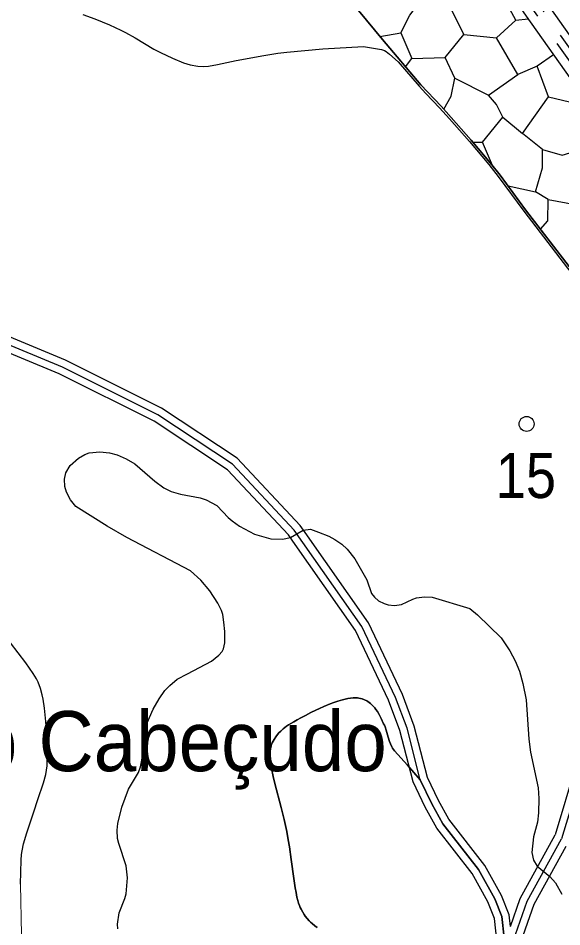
# Model space of a CAD drawing. Extents: x -64005 to -55000, y -89025 to -80000.
# Drawn here: x -58155 to -57432, y -86930 to -85720 of the extents above; entities that cross this region are included whole.
import ezdxf
from ezdxf.enums import TextEntityAlignment as Align

# ---------------------------------------------------------------- set-up
doc = ezdxf.new("R2010")
doc.units = 0
doc.header["$LTSCALE"] = 32
doc.linetypes.add('LONG_DASHED', pattern=[7.5, 6, -1.5])
for name, color, linetype, lineweight in [('1', 7, 'Continuous', 25), ('19', 7, 'Continuous', 25), ('2', 7, 'Continuous', 25), ('24', 7, 'Continuous', 25), ('39', 7, 'LONG_DASHED', 25), ('52', 7, 'Continuous', 25), ('6', 7, 'Continuous', 25), ('8', 7, 'Continuous', 25)]:
    doc.layers.add(name, color=color, linetype=linetype, lineweight=lineweight)
doc.layers.add('38', color=7, linetype='Continuous')
doc.layers.add('45', color=7, linetype='Continuous')

msp = doc.modelspace()

# ---------------------------------------------------------------- linework, layer by layer
at = {"layer": '1'}
for points in [[(-58022.62, -86932.62), (-58023.08, -86926.35), (-58020.77, -86910.96), (-58013.35, -86892.23), (-58011.68, -86885.82), (-58009.92, -86864.4), (-58011.54, -86848.71), (-58021.36, -86818.92), (-58022.93, -86812.2), (-58023.73, -86801.15), (-58022.57, -86791.95), (-58017.28, -86770.43), (-58008.67, -86746.26), (-57994.99, -86724.19), (-57992.41, -86716.67), (-57989.51, -86700.88), (-57986.13, -86668.4), (-57983.64, -86657.94), (-57975.7, -86639.8), (-57967.54, -86625.98), (-57960.05, -86615.21), (-57953.27, -86608.3), (-57943.57, -86599.99), (-57929.85, -86593.11), (-57898.08, -86576.04), (-57888.1, -86568.27), (-57884.06, -86563.32), (-57882.18, -86559.63), (-57880.41, -86551.71), (-57880.43, -86536.34), (-57881.46, -86524.08), (-57883.02, -86513.78), (-57884.68, -86508.56), (-57889.41, -86498.66), (-57900.36, -86482.24), (-57912.28, -86468.05), (-57925.94, -86455.92), (-58010.53, -86411.32), (-58037.05, -86396.29), (-58078.74, -86370), (-58085.82, -86361.23), (-58090.8, -86350.87), (-58093.06, -86343.4), (-58093.66, -86333.63), (-58091.85, -86325.19), (-58086.11, -86315.34), (-58075.12, -86305.68), (-58066.45, -86300.78), (-58060.95, -86298.85)], [(-58060.95, -86298.85), (-58046.6, -86297.24), (-58033.61, -86298.67), (-58023.54, -86301.46), (-58011.37, -86306.61), (-57999.84, -86313.53), (-57973.31, -86336.3), (-57961.31, -86345.31), (-57951.63, -86350.28), (-57939.2, -86353.8), (-57913.3, -86358.64), (-57905, -86361.23), (-57890.81, -86368.69), (-57882.9, -86377.06), (-57875.97, -86384.89), (-57870.37, -86389.28), (-57860.73, -86396.32), (-57840.89, -86406.82), (-57819.31, -86413.24), (-57803.56, -86413.83), (-57793.06, -86411.49), (-57776.14, -86401.57), (-57766.22, -86400.4), (-57755.58, -86404.08), (-57741.85, -86409.74), (-57733.88, -86413.92), (-57724.83, -86420.13), (-57717.47, -86427.07), (-57707.36, -86439.92), (-57691.53, -86467.61), (-57685.15, -86485.86), (-57681.25, -86491), (-57675.8, -86495.51), (-57668.19, -86499.43), (-57663.09, -86500.93), (-57654.49, -86501.77), (-57645.32, -86500.44), (-57630.36, -86493.36), (-57625.19, -86491.84), (-57614.74, -86490.41), (-57604.24, -86490.81), (-57554.53, -86506.04), (-57544.23, -86514.52), (-57512.82, -86545.15), (-57501.13, -86562.11), (-57494.05, -86575.42), (-57488.43, -86589.51), (-57483.64, -86605.74), (-57479.35, -86627.56), (-57475.75, -86679.87), (-57473.71, -86697.13), (-57463.41, -86744.72), (-57462.58, -86758.96), (-57462.93, -86778.13), (-57464.11, -86790.53), (-57469.48, -86809.71), (-57472, -86830.86), (-57469.57, -86840.81), (-57464.88, -86848.82), (-57448.02, -86862.68), (-57440.35, -86871.06), (-57431.91, -86886.4)]]:
    msp.add_lwpolyline(points, dxfattribs=at)
at = {"layer": '19'}
for p, q in [((-57492.92, -85722.5), (-57476.76, -85720.77)), ((-57639.92, -85784.58), (-57631.42, -85773.61)), ((-57524.16, -85916.19), (-57537.62, -85885.08))]:
    msp.add_line(p, q, dxfattribs=at)
for points in [[(-58127.34, -85120), (-57870.7, -85289.42), (-57711.55, -85422.38), (-57641.47, -85485.65), (-57474.02, -85724.68), (-57206.71, -86102.58), (-57203.97, -86106.46), (-57273.24, -86268.58)], [(-57554.12, -85671.82), (-57580.1, -85706.64), (-57562.49, -85741.88), (-57518.9, -85746.29), (-57492.92, -85722.5), (-57525.5, -85662.58)], [(-57673.9, -85744.25), (-57645.95, -85739.68), (-57634.06, -85715.88), (-57617.77, -85693.86)], [(-57273.24, -86268.58), (-57280.3, -86256.85), (-57288.99, -86240.05), (-57300.17, -86217.45), (-57306.34, -86206.47), (-57325.59, -86176.19), (-57340.53, -86153.31), (-57348.52, -86142.23), (-57380.22, -86103.46), (-57422.11, -86050.82), (-57480.14, -85974.96), (-57514.1, -85928.83), (-57526.62, -85913.1), (-57552.6, -85882.41), (-57592.51, -85837.14), (-57619.68, -85808.55), (-57670.35, -85748.55), (-57702.33, -85709.77)], [(-57645.95, -85739.68), (-57631.42, -85773.61), (-57586.95, -85772.29), (-57562.49, -85741.88)], [(-57442.91, -85768.65), (-57464.73, -85783.74), (-57490.28, -85794.76), (-57518.9, -85746.29)], [(-57589.13, -85840.98), (-57579.01, -85823.85), (-57574.18, -85800.05), (-57586.95, -85772.29)], [(-57574.18, -85800.05), (-57529.7, -85822.52), (-57490.28, -85794.76)], [(-57510.33, -85851.6), (-57484.34, -85873.63), (-57449.56, -85824.72), (-57464.73, -85783.74)], [(-57449.56, -85824.72), (-57421.82, -85831.33), (-57409.4, -85816.04)], [(-57550.23, -85885.22), (-57537.62, -85885.08), (-57510.33, -85851.6), (-57518.69, -85834.86), (-57529.7, -85822.52)], [(-57457.49, -85894.77), (-57431.52, -85902.26), (-57411.26, -85896.1), (-57401.12, -85843.22), (-57421.82, -85831.33)], [(-57503.53, -85943.19), (-57467.17, -85951.17), (-57457.49, -85919.44), (-57457.49, -85894.77), (-57484.34, -85873.63)], [(-57450.01, -85961.3), (-57414.33, -85967.91), (-57381.31, -85922.09)], [(-57460.39, -86000.77), (-57450.44, -85989.95), (-57450.01, -85961.3), (-57467.17, -85951.17)]]:
    msp.add_lwpolyline(points, dxfattribs=at)
at = {"layer": '2'}
msp.add_lwpolyline([(-58151.95, -86873.12), (-58151.22, -86840.83), (-58150.72, -86833.49), (-58150.05, -86828.65), (-58148.04, -86819.05), (-58143.86, -86804.81), (-58137.48, -86785.95), (-58134.54, -86776.51), (-58129.14, -86760.04), (-58121.63, -86738.14), (-58118.58, -86726.81), (-58116.9, -86715.22), (-58116.58, -86707.47), (-58116.77, -86691.99), (-58117.7, -86668.28), (-58118.57, -86656.43), (-58120.4, -86638.66), (-58122.1, -86626.79), (-58123.26, -86620.91), (-58125.59, -86612.25), (-58128.85, -86603.83), (-58130.91, -86599.74), (-58135.27, -86592.31), (-58144.91, -86578.33), (-58165.52, -86551.82)], dxfattribs=at)
at = {"layer": '2', "lineweight": 13}
msp.add_lwpolyline([(-58069.26, -87396.38), (-58086.31, -87327.48), (-58090.73, -87307.09), (-58093.13, -87293.38), (-58097.18, -87265.82), (-58101.96, -87228.09), (-58110.24, -87152.53), (-58110.75, -87146.28), (-58111.12, -87133.69), (-58111.5, -87116.9), (-58112.2, -87108.58), (-58113.58, -87100.37), (-58114.59, -87096.31), (-58119.23, -87080.74), (-58129.1, -87049.88), (-58145.06, -86999.71), (-58146.77, -86993.31), (-58149.06, -86980.3), (-58150.21, -86967.11), (-58150.86, -86940.59), (-58151.95, -86873.12)], dxfattribs=at)
at = {"layer": '24'}
for points in [[(-58069.4, -85715.19), (-58053.37, -85720.84), (-58033.97, -85728.97), (-58018.74, -85735.95), (-58012.25, -85739.21), (-57999.7, -85746.27), (-57974.73, -85761.11), (-57965.98, -85765.82), (-57949.94, -85773.45), (-57935.4, -85779.39), (-57926.6, -85782.08), (-57916.29, -85783.99), (-57908.9, -85784.34), (-57902.24, -85783.8), (-57889.87, -85781.51), (-57865.09, -85776.23), (-57828.22, -85769.58), (-57809.67, -85766.79), (-57797.74, -85765.34), (-57773.84, -85762.83), (-57749.92, -85760.82), (-57695.98, -85757.67), (-57671.77, -85761.62), (-57667.94, -85762.91), (-57665.57, -85764.31), (-57661.25, -85767.76)], [(-57661.25, -85767.76), (-57649.72, -85777.91), (-57621.92, -85810.55), (-57613.04, -85820.26), (-57594.72, -85839.17), (-57581.31, -85854.12), (-57554.88, -85884.36), (-57528.96, -85914.99), (-57516.46, -85930.68), (-57482.54, -85976.76), (-57424.48, -86052.67), (-57382.56, -86105.34), (-57357.83, -86135.32), (-57350.93, -86144.03), (-57342.98, -86155.06), (-57315.2, -86197.84), (-57308.94, -86207.97), (-57299.9, -86224.55), (-57288.8, -86247.19), (-57282.91, -86258.34), (-57275.17, -86271.52), (-57358.49, -86549.13)], [(-57820.09, -86695.98), (-57819.61, -86692.66), (-57818.71, -86688.88), (-57818.06, -86686.88), (-57817.23, -86684.77), (-57816.18, -86682.53), (-57814.86, -86680.17), (-57812.55, -86676.67), (-57810.08, -86673.48), (-57808.35, -86671.51), (-57805.96, -86669.06), (-57802.61, -86666.07), (-57800.63, -86664.49), (-57798.3, -86662.77), (-57795.56, -86660.92), (-57792.35, -86658.91), (-57788.57, -86656.73), (-57784.15, -86654.31), (-57778.98, -86651.56), (-57772.97, -86648.31), (-57766.08, -86644.61), (-57759.18, -86641.14), (-57754.57, -86638.96), (-57748.41, -86636.25), (-57740.18, -86632.96), (-57735.47, -86631.25), (-57730.07, -86629.47), (-57723.88, -86627.66), (-57716.78, -86625.88), (-57713.26, -86625.24), (-57709.63, -86624.9), (-57707.17, -86624.86), (-57703.87, -86625.05), (-57701.98, -86625.3), (-57699.83, -86625.72), (-57697.39, -86626.38), (-57694.63, -86627.39), (-57691.56, -86628.89), (-57689.97, -86629.85), (-57688.3, -86631), (-57686.57, -86632.38), (-57684.19, -86634.57), (-57682.07, -86636.8), (-57680.78, -86638.31), (-57679.2, -86640.37), (-57677.31, -86643.15), (-57675.09, -86646.95), (-57672.45, -86652.17), (-57669.03, -86659.35), (-57668.07, -86661.46), (-57667.2, -86663.63), (-57665.69, -86668.07), (-57663.09, -86677.13), (-57661.23, -86683.06), (-57659.97, -86686.32), (-57658.26, -86689.88), (-57657.2, -86691.69), (-57655.93, -86693.54), (-57654.41, -86695.41), (-57637.31, -86714.68), (-57620.21, -86733.94)], [(-57620.21, -86733.94), (-57637.31, -86714.68), (-57654.41, -86695.41), (-57655.93, -86693.54), (-57657.2, -86691.69), (-57658.26, -86689.88), (-57659.97, -86686.32), (-57661.23, -86683.06), (-57663.09, -86677.13), (-57665.69, -86668.07), (-57667.2, -86663.63), (-57668.07, -86661.46), (-57669.03, -86659.35), (-57672.45, -86652.17), (-57675.09, -86646.95), (-57677.31, -86643.15), (-57679.2, -86640.37), (-57680.78, -86638.31), (-57682.07, -86636.8), (-57684.19, -86634.57), (-57686.57, -86632.38), (-57688.3, -86631), (-57689.97, -86629.85), (-57691.56, -86628.89), (-57694.63, -86627.39), (-57697.39, -86626.38), (-57699.83, -86625.72), (-57701.98, -86625.3), (-57703.87, -86625.05), (-57707.17, -86624.86), (-57709.63, -86624.9), (-57713.26, -86625.24), (-57716.78, -86625.88), (-57723.88, -86627.66), (-57730.07, -86629.47), (-57735.47, -86631.25), (-57740.18, -86632.96), (-57748.41, -86636.25), (-57754.57, -86638.96), (-57759.18, -86641.14), (-57766.08, -86644.61), (-57772.97, -86648.31), (-57778.98, -86651.56), (-57784.15, -86654.31), (-57788.57, -86656.73), (-57792.35, -86658.91), (-57795.56, -86660.92), (-57798.3, -86662.77), (-57800.63, -86664.49), (-57802.61, -86666.07), (-57805.96, -86669.06), (-57808.35, -86671.51), (-57810.08, -86673.48), (-57812.55, -86676.67), (-57814.86, -86680.17), (-57816.18, -86682.53), (-57817.23, -86684.77), (-57818.06, -86686.88), (-57818.71, -86688.88), (-57819.61, -86692.66), (-57820.09, -86695.98)], [(-57757.46, -86930.51), (-57760.7, -86928.22), (-57764.29, -86925.28), (-57766.14, -86923.56), (-57768.06, -86921.59), (-57770.77, -86918.51), (-57773.23, -86915.36), (-57774.74, -86913.23), (-57776.58, -86910.34), (-57778.76, -86906.39), (-57779.87, -86904.09), (-57781.01, -86901.42), (-57782.16, -86898.3), (-57783.28, -86894.66), (-57784.31, -86890.4), (-57785.55, -86884.14), (-57786.68, -86877.87), (-57788.68, -86865.29), (-57792.13, -86840.09), (-57794.47, -86823.34), (-57795.98, -86813.81), (-57797.95, -86802.99), (-57799.63, -86794.95), (-57801.46, -86786.91), (-57805.41, -86770.87), (-57813.61, -86738.81), (-57815.8, -86729.64), (-57818.1, -86719.16), (-57819.05, -86714.26), (-57819.8, -86709.29), (-57820.15, -86705.94), (-57820.35, -86701.47), (-57820.31, -86698.91), (-57820.09, -86695.98)], [(-57820.09, -86695.98), (-57820.31, -86698.91), (-57820.35, -86701.47), (-57820.15, -86705.94), (-57819.8, -86709.29), (-57819.05, -86714.26), (-57818.1, -86719.16), (-57815.8, -86729.64), (-57813.61, -86738.81), (-57805.41, -86770.87), (-57801.46, -86786.91), (-57799.63, -86794.95), (-57797.95, -86802.99), (-57795.98, -86813.81), (-57794.47, -86823.34), (-57792.13, -86840.09), (-57788.68, -86865.29), (-57786.68, -86877.87), (-57785.55, -86884.14), (-57784.31, -86890.4), (-57783.28, -86894.66), (-57782.16, -86898.3), (-57781.01, -86901.42), (-57779.87, -86904.09), (-57778.76, -86906.39), (-57776.58, -86910.34), (-57774.74, -86913.23), (-57773.23, -86915.36), (-57770.77, -86918.51), (-57768.06, -86921.59), (-57766.14, -86923.56), (-57764.29, -86925.28), (-57760.7, -86928.22), (-57757.46, -86930.51)], [(-57620.21, -86733.94), (-57605, -86765.98), (-57590.18, -86792.4), (-57542.7, -86853.41), (-57521.15, -86892.38), (-57511.91, -86916.2), (-57508.84, -86944.35), (-57496.52, -86964.56), (-57473.43, -86993.42), (-57447.61, -87031.68)], [(-57447.61, -87031.68), (-57473.43, -86993.42), (-57496.52, -86964.56), (-57508.84, -86944.35), (-57511.91, -86916.2), (-57521.15, -86892.38), (-57542.7, -86853.41), (-57590.18, -86792.4), (-57605, -86765.98), (-57620.21, -86733.94)]]:
    msp.add_lwpolyline(points, dxfattribs=at)
at = {"layer": '39'}
for points in [[(-57184.19, -86095.45), (-57455.62, -85711.72), (-57624.49, -85470.66), (-57696.79, -85405.39), (-57857.24, -85271.34), (-58121.75, -85096.73), (-58127.61, -85092.2)], [(-57500.05, -86958.76), (-57508.84, -86944.35), (-57511.91, -86916.2), (-57521.15, -86892.38), (-57542.7, -86853.41), (-57590.18, -86792.4), (-57605, -86765.98), (-57620.21, -86733.94), (-57637.91, -86665.38), (-57653.3, -86624.24), (-57697.81, -86530.1), (-57787.87, -86401.63), (-57870.22, -86313.6), (-57969.5, -86247.93), (-58096.5, -86184.43), (-58237.35, -86125.98), (-58284.93, -86108.85), (-58355.74, -86078.54), (-58426.55, -86038.86), (-58465.7, -86013.75), (-58487.25, -86002.2), (-58498.02, -85987.05)], [(-57281.21, -86340.17), (-57290.79, -86335.56), (-57303.1, -86336.86), (-57319.3, -86347.24), (-57332.26, -86362.8), (-57341.98, -86385.49), (-57342.62, -86405.59), (-57339.38, -86442.54), (-57365.29, -86531.37), (-57390.55, -86638.02), (-57404.15, -86719.06), (-57432.32, -86812.66)], [(-57500.05, -86958.76), (-57478.03, -86895.73), (-57432.32, -86812.66)]]:
    msp.add_lwpolyline(points, dxfattribs=at)
at = {"layer": '52'}
msp.add_circle((-57478.8, -86260.23), 10, dxfattribs=at)
at = {"layer": '6', "lineweight": 35}
msp.add_lwpolyline([(-57273.24, -86268.58), (-57280.3, -86256.85), (-57288.99, -86240.05), (-57300.17, -86217.45), (-57306.34, -86206.47), (-57325.59, -86176.19), (-57340.53, -86153.31), (-57348.52, -86142.23), (-57380.22, -86103.46), (-57422.11, -86050.82), (-57480.14, -85974.96), (-57514.1, -85928.83), (-57526.62, -85913.1), (-57552.6, -85882.41), (-57592.51, -85837.14), (-57619.68, -85808.55), (-57670.35, -85748.55), (-57702.33, -85709.77)], dxfattribs=at)
at = {"layer": '8'}
for points in [[(-57179.6, -86084.63), (-57447.44, -85705.96), (-57616.95, -85464), (-57690.23, -85397.84), (-57851.26, -85263.31), (-58111.79, -85091.32)], [(-57789.75, -86416.37), (-57795.65, -86407.95), (-57876.72, -86321.29), (-57974.51, -86256.6), (-58100.66, -86193.53), (-58240.96, -86135.31), (-58288.6, -86118.16), (-58360.17, -86087.52), (-58431.7, -86047.44), (-58470.77, -86022.38), (-58489.17, -86012.52)], [(-57500.41, -86929.45), (-57502.11, -86913.81), (-57512.07, -86888.13), (-57534.33, -86847.89), (-57582.21, -86786.35), (-57596.12, -86761.37), (-57610.61, -86731.11), (-57628.36, -86662.37), (-57644.08, -86620.34), (-57689.13, -86525.06), (-57773.5, -86404.72)], [(-57489.12, -86957.79), (-57468.74, -86899.49), (-57426.31, -86822.41)]]:
    msp.add_lwpolyline(points, dxfattribs=at)
at = {"layer": '8', "linetype": 'LONG_DASHED'}
for points in [[(-57188.79, -86106.26), (-57463.8, -85717.48), (-57632.03, -85477.32), (-57703.35, -85412.94), (-57863.23, -85279.37), (-58128.58, -85104.2)], [(-57773.5, -86404.72), (-57780.09, -86395.31), (-57863.72, -86305.91), (-57964.49, -86239.25), (-58092.34, -86175.33), (-58233.74, -86116.65), (-58281.26, -86099.53), (-58351.31, -86069.56), (-58421.4, -86030.28), (-58460.63, -86005.12), (-58480.46, -85994.49)], [(-57277.86, -86330.69), (-57289.01, -86325.32), (-57306.5, -86327.16), (-57326, -86339.65), (-57340.88, -86357.52), (-57351.91, -86383.29), (-57352.63, -86405.87), (-57349.51, -86441.54), (-57374.96, -86528.82), (-57400.36, -86636.04), (-57413.91, -86716.78), (-57440.79, -86807.38)], [(-57456.03, -87037.07), (-57481.49, -86999.35), (-57504.73, -86970.31), (-57518.54, -86947.65), (-57521.71, -86918.59), (-57530.23, -86896.63), (-57551.07, -86858.93), (-57598.15, -86798.45), (-57613.88, -86770.6), (-57629.81, -86736.77), (-57647.46, -86668.39), (-57662.52, -86628.14), (-57706.49, -86535.14), (-57789.75, -86416.37)], [(-57500.41, -86929.45), (-57487.31, -86891.97), (-57440.79, -86807.38)]]:
    msp.add_lwpolyline(points, dxfattribs=at)

# ---------------------------------------------------------------- texts
at = {"layer": '38', "width": 0.9}
msp.add_text('15', height=60, rotation=0.007, dxfattribs=at).set_placement((-57479.77, -86358.86), align=Align.CENTER)
at = {"layer": '45', "width": 0.95}
msp.add_text('Mte. do Pinhal do Cabeçudo', height=80, rotation=0.007, dxfattribs=at).set_placement((-58306.11, -86722.53), align=Align.CENTER)

doc.saveas('drawing.dxf')
